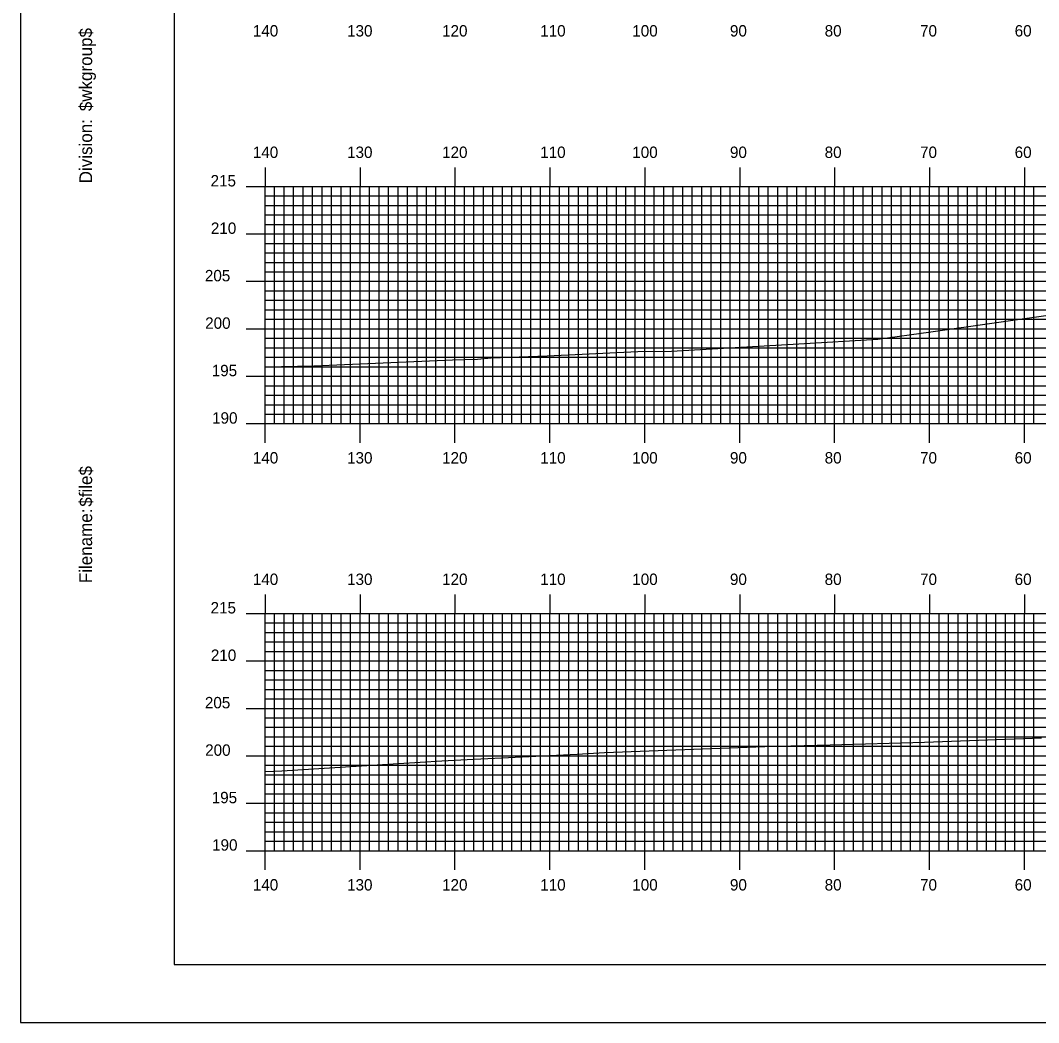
# Model space of a CAD drawing. Extents: x 1821998 to 1822342, y 442591 to 442811.
# Drawn here: x 1821998.5 to 1822105.8, y 442590.5 to 442696.2 of the extents above; entities that cross this region are included whole.
import ezdxf

# ---------------------------------------------------------------- set-up
doc = ezdxf.new("R2010")
doc.units = 0
for name, color, linetype in [('BORDER', 7, 'Continuous'), ('H_V ANNOTATION', 7, 'Continuous'), ('MAJOR', 7, 'Continuous'), ('MINOR', 7, 'Continuous'), ('PLOT BOUNDARY', 7, 'Continuous'), ('S_Roadway_Centerline', 7, 'Continuous')]:
    doc.layers.add(name, color=color, linetype=linetype)

msp = doc.modelspace()

# ---------------------------------------------------------------- linework, layer by layer
at = {"layer": 'BORDER'}
msp.add_lwpolyline([(1822014.66, 442596.67), (1822334.66, 442596.67), (1822334.66, 442806.67), (1822014.66, 442806.67)], close=True, dxfattribs=at)
at = {"layer": 'MAJOR'}
for p, q in [((1822024.26, 442680.67), (1822024.26, 442678.67)), ((1822034.26, 442680.67), (1822034.26, 442678.67)), ((1822044.26, 442680.67), (1822044.26, 442678.67)), ((1822054.26, 442680.67), (1822054.26, 442678.67)), ((1822064.26, 442680.67), (1822064.26, 442678.67)), ((1822074.26, 442680.67), (1822074.26, 442678.67)), ((1822084.26, 442680.67), (1822084.26, 442678.67)), ((1822094.26, 442680.67), (1822094.26, 442678.67)), ((1822104.26, 442680.67), (1822104.26, 442678.67)), ((1822022.25, 442678.67), (1822024.26, 442678.67)), ((1822024.26, 442678.67), (1822304.26, 442678.67)), ((1822024.26, 442653.67), (1822024.26, 442678.67)), ((1822024.26, 442653.67), (1822024.26, 442678.67)), ((1822024.26, 442678.67), (1822304.26, 442678.67)), ((1822034.26, 442653.67), (1822034.26, 442678.67)), ((1822044.26, 442653.67), (1822044.26, 442678.67)), ((1822054.26, 442653.67), (1822054.26, 442678.67)), ((1822064.26, 442653.67), (1822064.26, 442678.67)), ((1822074.26, 442653.67), (1822074.26, 442678.67)), ((1822084.26, 442653.67), (1822084.26, 442678.67)), ((1822094.26, 442653.67), (1822094.26, 442678.67)), ((1822104.26, 442653.67), (1822104.26, 442678.67)), ((1822022.25, 442673.67), (1822024.26, 442673.67)), ((1822024.26, 442673.67), (1822304.26, 442673.67)), ((1822022.25, 442668.67), (1822024.26, 442668.67)), ((1822024.26, 442668.67), (1822304.26, 442668.67)), ((1822022.25, 442663.67), (1822024.26, 442663.67)), ((1822024.26, 442663.67), (1822304.26, 442663.67)), ((1822022.25, 442658.67), (1822024.26, 442658.67)), ((1822024.26, 442658.67), (1822304.26, 442658.67)), ((1822022.25, 442653.67), (1822024.26, 442653.67)), ((1822024.26, 442653.67), (1822304.26, 442653.67)), ((1822024.26, 442653.67), (1822304.26, 442653.67)), ((1822024.26, 442651.66), (1822024.26, 442653.67)), ((1822034.26, 442651.66), (1822034.26, 442653.67)), ((1822044.26, 442651.66), (1822044.26, 442653.67)), ((1822054.26, 442651.66), (1822054.26, 442653.67)), ((1822064.26, 442651.66), (1822064.26, 442653.67)), ((1822074.26, 442651.66), (1822074.26, 442653.67)), ((1822084.26, 442651.66), (1822084.26, 442653.67)), ((1822094.26, 442651.66), (1822094.26, 442653.67)), ((1822104.26, 442651.66), (1822104.26, 442653.67)), ((1822024.26, 442635.67), (1822024.26, 442633.67)), ((1822034.26, 442635.67), (1822034.26, 442633.67)), ((1822044.26, 442635.67), (1822044.26, 442633.67)), ((1822054.26, 442635.67), (1822054.26, 442633.67)), ((1822064.26, 442635.67), (1822064.26, 442633.67)), ((1822074.26, 442635.67), (1822074.26, 442633.67)), ((1822084.26, 442635.67), (1822084.26, 442633.67)), ((1822094.26, 442635.67), (1822094.26, 442633.67)), ((1822104.26, 442635.67), (1822104.26, 442633.67)), ((1822022.25, 442633.67), (1822024.26, 442633.67)), ((1822024.26, 442633.67), (1822304.26, 442633.67)), ((1822024.26, 442608.67), (1822024.26, 442633.67)), ((1822024.26, 442608.67), (1822024.26, 442633.67)), ((1822024.26, 442633.67), (1822304.26, 442633.67)), ((1822034.26, 442608.67), (1822034.26, 442633.67)), ((1822044.26, 442608.67), (1822044.26, 442633.67)), ((1822054.26, 442608.67), (1822054.26, 442633.67)), ((1822064.26, 442608.67), (1822064.26, 442633.67)), ((1822074.26, 442608.67), (1822074.26, 442633.67)), ((1822084.26, 442608.67), (1822084.26, 442633.67)), ((1822094.26, 442608.67), (1822094.26, 442633.67)), ((1822104.26, 442608.67), (1822104.26, 442633.67)), ((1822022.25, 442628.67), (1822024.26, 442628.67)), ((1822024.26, 442628.67), (1822304.26, 442628.67)), ((1822022.25, 442623.67), (1822024.26, 442623.67)), ((1822024.26, 442623.67), (1822304.26, 442623.67)), ((1822022.25, 442618.67), (1822024.26, 442618.67)), ((1822024.26, 442618.67), (1822304.26, 442618.67)), ((1822022.25, 442613.67), (1822024.26, 442613.67)), ((1822024.26, 442613.67), (1822304.26, 442613.67)), ((1822022.25, 442608.67), (1822024.26, 442608.67)), ((1822024.26, 442608.67), (1822304.26, 442608.67)), ((1822024.26, 442608.67), (1822304.26, 442608.67)), ((1822024.26, 442606.66), (1822024.26, 442608.67)), ((1822034.26, 442606.66), (1822034.26, 442608.67)), ((1822044.26, 442606.66), (1822044.26, 442608.67)), ((1822054.26, 442606.66), (1822054.26, 442608.67)), ((1822064.26, 442606.66), (1822064.26, 442608.67)), ((1822074.26, 442606.66), (1822074.26, 442608.67)), ((1822084.26, 442606.66), (1822084.26, 442608.67)), ((1822094.26, 442606.66), (1822094.26, 442608.67)), ((1822104.26, 442606.66), (1822104.26, 442608.67))]:
    msp.add_line(p, q, dxfattribs=at)
at = {"layer": 'MINOR'}
for p, q in [((1822025.26, 442653.67), (1822025.26, 442678.67)), ((1822026.26, 442653.67), (1822026.26, 442678.67)), ((1822027.26, 442653.67), (1822027.26, 442678.67)), ((1822028.26, 442653.67), (1822028.26, 442678.67)), ((1822029.26, 442653.67), (1822029.26, 442678.67)), ((1822030.26, 442653.67), (1822030.26, 442678.67)), ((1822031.26, 442653.67), (1822031.26, 442678.67)), ((1822032.26, 442653.67), (1822032.26, 442678.67)), ((1822033.26, 442653.67), (1822033.26, 442678.67)), ((1822035.26, 442653.67), (1822035.26, 442678.67)), ((1822036.26, 442653.67), (1822036.26, 442678.67)), ((1822037.26, 442653.67), (1822037.26, 442678.67)), ((1822038.26, 442653.67), (1822038.26, 442678.67)), ((1822039.26, 442653.67), (1822039.26, 442678.67)), ((1822040.26, 442653.67), (1822040.26, 442678.67)), ((1822041.26, 442653.67), (1822041.26, 442678.67)), ((1822042.26, 442653.67), (1822042.26, 442678.67)), ((1822043.26, 442653.67), (1822043.26, 442678.67)), ((1822045.26, 442653.67), (1822045.26, 442678.67)), ((1822046.26, 442653.67), (1822046.26, 442678.67)), ((1822047.26, 442653.67), (1822047.26, 442678.67)), ((1822048.26, 442653.67), (1822048.26, 442678.67)), ((1822049.26, 442653.67), (1822049.26, 442678.67)), ((1822050.26, 442653.67), (1822050.26, 442678.67)), ((1822051.26, 442653.67), (1822051.26, 442678.67)), ((1822052.26, 442653.67), (1822052.26, 442678.67)), ((1822053.26, 442653.67), (1822053.26, 442678.67)), ((1822055.26, 442653.67), (1822055.26, 442678.67)), ((1822056.26, 442653.67), (1822056.26, 442678.67)), ((1822057.26, 442653.67), (1822057.26, 442678.67)), ((1822058.26, 442653.67), (1822058.26, 442678.67)), ((1822059.26, 442653.67), (1822059.26, 442678.67)), ((1822060.26, 442653.67), (1822060.26, 442678.67)), ((1822061.26, 442653.67), (1822061.26, 442678.67)), ((1822062.26, 442653.67), (1822062.26, 442678.67)), ((1822063.26, 442653.67), (1822063.26, 442678.67)), ((1822065.26, 442653.67), (1822065.26, 442678.67)), ((1822066.26, 442653.67), (1822066.26, 442678.67)), ((1822067.26, 442653.67), (1822067.26, 442678.67)), ((1822068.26, 442653.67), (1822068.26, 442678.67)), ((1822069.26, 442653.67), (1822069.26, 442678.67)), ((1822070.26, 442653.67), (1822070.26, 442678.67)), ((1822071.26, 442653.67), (1822071.26, 442678.67)), ((1822072.26, 442653.67), (1822072.26, 442678.67)), ((1822073.26, 442653.67), (1822073.26, 442678.67)), ((1822075.26, 442653.67), (1822075.26, 442678.67)), ((1822076.26, 442653.67), (1822076.26, 442678.67)), ((1822077.26, 442653.67), (1822077.26, 442678.67)), ((1822078.26, 442653.67), (1822078.26, 442678.67)), ((1822079.26, 442653.67), (1822079.26, 442678.67)), ((1822080.26, 442653.67), (1822080.26, 442678.67)), ((1822081.26, 442653.67), (1822081.26, 442678.67)), ((1822082.26, 442653.67), (1822082.26, 442678.67)), ((1822083.26, 442653.67), (1822083.26, 442678.67)), ((1822085.26, 442653.67), (1822085.26, 442678.67)), ((1822086.26, 442653.67), (1822086.26, 442678.67)), ((1822087.26, 442653.67), (1822087.26, 442678.67)), ((1822088.26, 442653.67), (1822088.26, 442678.67)), ((1822089.26, 442653.67), (1822089.26, 442678.67)), ((1822090.26, 442653.67), (1822090.26, 442678.67)), ((1822091.26, 442653.67), (1822091.26, 442678.67)), ((1822092.26, 442653.67), (1822092.26, 442678.67)), ((1822093.26, 442653.67), (1822093.26, 442678.67)), ((1822095.26, 442653.67), (1822095.26, 442678.67)), ((1822096.26, 442653.67), (1822096.26, 442678.67)), ((1822097.26, 442653.67), (1822097.26, 442678.67)), ((1822098.26, 442653.67), (1822098.26, 442678.67)), ((1822099.26, 442653.67), (1822099.26, 442678.67)), ((1822100.26, 442653.67), (1822100.26, 442678.67)), ((1822101.26, 442653.67), (1822101.26, 442678.67)), ((1822102.26, 442653.67), (1822102.26, 442678.67)), ((1822103.26, 442653.67), (1822103.26, 442678.67)), ((1822105.26, 442653.67), (1822105.26, 442678.67)), ((1822024.26, 442677.67), (1822304.26, 442677.67)), ((1822024.26, 442677.67), (1822026.26, 442677.67)), ((1822024.26, 442676.67), (1822304.26, 442676.67)), ((1822024.26, 442676.67), (1822026.26, 442676.67)), ((1822024.26, 442675.67), (1822304.26, 442675.67)), ((1822024.26, 442675.67), (1822026.26, 442675.67)), ((1822024.26, 442674.67), (1822304.26, 442674.67)), ((1822024.26, 442674.67), (1822026.26, 442674.67)), ((1822024.26, 442672.67), (1822304.26, 442672.67)), ((1822024.26, 442672.67), (1822026.26, 442672.67)), ((1822024.26, 442671.67), (1822304.26, 442671.67)), ((1822024.26, 442671.67), (1822026.26, 442671.67)), ((1822024.26, 442670.67), (1822304.26, 442670.67)), ((1822024.26, 442670.67), (1822026.26, 442670.67)), ((1822024.26, 442669.67), (1822304.26, 442669.67)), ((1822024.26, 442669.67), (1822026.26, 442669.67)), ((1822024.26, 442667.67), (1822304.26, 442667.67)), ((1822024.26, 442667.67), (1822026.26, 442667.67)), ((1822024.26, 442666.67), (1822304.26, 442666.67)), ((1822024.26, 442666.67), (1822026.26, 442666.67)), ((1822024.26, 442665.67), (1822304.26, 442665.67)), ((1822024.26, 442665.67), (1822026.26, 442665.67)), ((1822024.26, 442664.67), (1822304.26, 442664.67)), ((1822024.26, 442664.67), (1822026.26, 442664.67)), ((1822024.26, 442662.67), (1822304.26, 442662.67)), ((1822024.26, 442662.67), (1822026.26, 442662.67)), ((1822024.26, 442661.67), (1822304.26, 442661.67)), ((1822024.26, 442661.67), (1822026.26, 442661.67)), ((1822024.26, 442660.67), (1822304.26, 442660.67)), ((1822024.26, 442660.67), (1822026.26, 442660.67)), ((1822024.26, 442659.67), (1822304.26, 442659.67)), ((1822024.26, 442659.67), (1822026.26, 442659.67)), ((1822024.26, 442657.67), (1822304.26, 442657.67)), ((1822024.26, 442657.67), (1822026.26, 442657.67)), ((1822024.26, 442656.67), (1822304.26, 442656.67)), ((1822024.26, 442656.67), (1822026.26, 442656.67)), ((1822024.26, 442655.67), (1822304.26, 442655.67)), ((1822024.26, 442655.67), (1822026.26, 442655.67)), ((1822024.26, 442654.67), (1822304.26, 442654.67)), ((1822024.26, 442654.67), (1822026.26, 442654.67)), ((1822025.26, 442608.67), (1822025.26, 442633.67)), ((1822026.26, 442608.67), (1822026.26, 442633.67)), ((1822027.26, 442608.67), (1822027.26, 442633.67)), ((1822028.26, 442608.67), (1822028.26, 442633.67)), ((1822029.26, 442608.67), (1822029.26, 442633.67)), ((1822030.26, 442608.67), (1822030.26, 442633.67)), ((1822031.26, 442608.67), (1822031.26, 442633.67)), ((1822032.26, 442608.67), (1822032.26, 442633.67)), ((1822033.26, 442608.67), (1822033.26, 442633.67)), ((1822035.26, 442608.67), (1822035.26, 442633.67)), ((1822036.26, 442608.67), (1822036.26, 442633.67)), ((1822037.26, 442608.67), (1822037.26, 442633.67)), ((1822038.26, 442608.67), (1822038.26, 442633.67)), ((1822039.26, 442608.67), (1822039.26, 442633.67)), ((1822040.26, 442608.67), (1822040.26, 442633.67)), ((1822041.26, 442608.67), (1822041.26, 442633.67)), ((1822042.26, 442608.67), (1822042.26, 442633.67)), ((1822043.26, 442608.67), (1822043.26, 442633.67)), ((1822045.26, 442608.67), (1822045.26, 442633.67)), ((1822046.26, 442608.67), (1822046.26, 442633.67)), ((1822047.26, 442608.67), (1822047.26, 442633.67)), ((1822048.26, 442608.67), (1822048.26, 442633.67)), ((1822049.26, 442608.67), (1822049.26, 442633.67)), ((1822050.26, 442608.67), (1822050.26, 442633.67)), ((1822051.26, 442608.67), (1822051.26, 442633.67)), ((1822052.26, 442608.67), (1822052.26, 442633.67)), ((1822053.26, 442608.67), (1822053.26, 442633.67)), ((1822055.26, 442608.67), (1822055.26, 442633.67)), ((1822056.26, 442608.67), (1822056.26, 442633.67)), ((1822057.26, 442608.67), (1822057.26, 442633.67)), ((1822058.26, 442608.67), (1822058.26, 442633.67)), ((1822059.26, 442608.67), (1822059.26, 442633.67)), ((1822060.26, 442608.67), (1822060.26, 442633.67)), ((1822061.26, 442608.67), (1822061.26, 442633.67)), ((1822062.26, 442608.67), (1822062.26, 442633.67)), ((1822063.26, 442608.67), (1822063.26, 442633.67)), ((1822065.26, 442608.67), (1822065.26, 442633.67)), ((1822066.26, 442608.67), (1822066.26, 442633.67)), ((1822067.26, 442608.67), (1822067.26, 442633.67)), ((1822068.26, 442608.67), (1822068.26, 442633.67)), ((1822069.26, 442608.67), (1822069.26, 442633.67)), ((1822070.26, 442608.67), (1822070.26, 442633.67)), ((1822071.26, 442608.67), (1822071.26, 442633.67)), ((1822072.26, 442608.67), (1822072.26, 442633.67)), ((1822073.26, 442608.67), (1822073.26, 442633.67)), ((1822075.26, 442608.67), (1822075.26, 442633.67)), ((1822076.26, 442608.67), (1822076.26, 442633.67)), ((1822077.26, 442608.67), (1822077.26, 442633.67)), ((1822078.26, 442608.67), (1822078.26, 442633.67)), ((1822079.26, 442608.67), (1822079.26, 442633.67)), ((1822080.26, 442608.67), (1822080.26, 442633.67)), ((1822081.26, 442608.67), (1822081.26, 442633.67)), ((1822082.26, 442608.67), (1822082.26, 442633.67)), ((1822083.26, 442608.67), (1822083.26, 442633.67)), ((1822085.26, 442608.67), (1822085.26, 442633.67)), ((1822086.26, 442608.67), (1822086.26, 442633.67)), ((1822087.26, 442608.67), (1822087.26, 442633.67)), ((1822088.26, 442608.67), (1822088.26, 442633.67)), ((1822089.26, 442608.67), (1822089.26, 442633.67)), ((1822090.26, 442608.67), (1822090.26, 442633.67)), ((1822091.26, 442608.67), (1822091.26, 442633.67)), ((1822092.26, 442608.67), (1822092.26, 442633.67)), ((1822093.26, 442608.67), (1822093.26, 442633.67)), ((1822095.26, 442608.67), (1822095.26, 442633.67)), ((1822096.26, 442608.67), (1822096.26, 442633.67)), ((1822097.26, 442608.67), (1822097.26, 442633.67)), ((1822098.26, 442608.67), (1822098.26, 442633.67)), ((1822099.26, 442608.67), (1822099.26, 442633.67)), ((1822100.26, 442608.67), (1822100.26, 442633.67)), ((1822101.26, 442608.67), (1822101.26, 442633.67)), ((1822102.26, 442608.67), (1822102.26, 442633.67)), ((1822103.26, 442608.67), (1822103.26, 442633.67)), ((1822105.26, 442608.67), (1822105.26, 442633.67)), ((1822024.26, 442632.67), (1822304.26, 442632.67)), ((1822024.26, 442632.67), (1822026.26, 442632.67)), ((1822024.26, 442631.67), (1822304.26, 442631.67)), ((1822024.26, 442631.67), (1822026.26, 442631.67)), ((1822024.26, 442630.67), (1822304.26, 442630.67)), ((1822024.26, 442630.67), (1822026.26, 442630.67)), ((1822024.26, 442629.67), (1822304.26, 442629.67)), ((1822024.26, 442629.67), (1822026.26, 442629.67)), ((1822024.26, 442627.67), (1822304.26, 442627.67)), ((1822024.26, 442627.67), (1822026.26, 442627.67)), ((1822024.26, 442626.67), (1822304.26, 442626.67)), ((1822024.26, 442626.67), (1822026.26, 442626.67)), ((1822024.26, 442625.67), (1822304.26, 442625.67)), ((1822024.26, 442625.67), (1822026.26, 442625.67)), ((1822024.26, 442624.67), (1822304.26, 442624.67)), ((1822024.26, 442624.67), (1822026.26, 442624.67)), ((1822024.26, 442622.67), (1822304.26, 442622.67)), ((1822024.26, 442622.67), (1822026.26, 442622.67)), ((1822024.26, 442621.67), (1822304.26, 442621.67)), ((1822024.26, 442621.67), (1822026.26, 442621.67)), ((1822024.26, 442620.67), (1822304.26, 442620.67)), ((1822024.26, 442620.67), (1822026.26, 442620.67)), ((1822024.26, 442619.67), (1822304.26, 442619.67)), ((1822024.26, 442619.67), (1822026.26, 442619.67)), ((1822024.26, 442617.67), (1822304.26, 442617.67)), ((1822024.26, 442617.67), (1822026.26, 442617.67)), ((1822024.26, 442616.67), (1822304.26, 442616.67)), ((1822024.26, 442616.67), (1822026.26, 442616.67)), ((1822024.26, 442615.67), (1822304.26, 442615.67)), ((1822024.26, 442615.67), (1822026.26, 442615.67)), ((1822024.26, 442614.67), (1822304.26, 442614.67)), ((1822024.26, 442614.67), (1822026.26, 442614.67)), ((1822024.26, 442612.67), (1822304.26, 442612.67)), ((1822024.26, 442612.67), (1822026.26, 442612.67)), ((1822024.26, 442611.67), (1822304.26, 442611.67)), ((1822024.26, 442611.67), (1822026.26, 442611.67)), ((1822024.26, 442610.67), (1822304.26, 442610.67)), ((1822024.26, 442610.67), (1822026.26, 442610.67)), ((1822024.26, 442609.67), (1822304.26, 442609.67)), ((1822024.26, 442609.67), (1822026.26, 442609.67))]:
    msp.add_line(p, q, dxfattribs=at)
at = {"layer": 'PLOT BOUNDARY'}
msp.add_lwpolyline([(1821998.47, 442590.55), (1822338.47, 442590.55), (1822338.47, 442810.55), (1821998.47, 442810.55)], close=True, dxfattribs=at)
at = {"layer": 'S_Roadway_Centerline'}
for points in [[(1822024.26, 442659.65), (1822029.39, 442659.75), (1822043.99, 442660.38), (1822046.65, 442660.47), (1822048.06, 442660.61), (1822053.98, 442660.81), (1822063.52, 442661.27), (1822067.07, 442661.32), (1822080.49, 442662.08), (1822088.82, 442662.58), (1822094.4, 442663.34), (1822107.97, 442665.29)], [(1822024.26, 442617.03), (1822026.03, 442617.08), (1822038.31, 442617.87), (1822042.88, 442618.12), (1822045.56, 442618.27), (1822057.12, 442618.85), (1822060.02, 442619), (1822060.97, 442619.04), (1822076.89, 442619.66), (1822083.79, 442619.81), (1822093.73, 442620.12), (1822106.05, 442620.56)]]:
    msp.add_lwpolyline(points, dxfattribs=at)

# ---------------------------------------------------------------- texts
at = {"layer": 'BORDER'}
for s, p in [('$wkgroup$', (1822006.03, 442686.6)), ('Division:', (1822006.03, 442679)), ('$file$', (1822006.03, 442644.92)), ('Filename:', (1822006.03, 442636.86))]:
    msp.add_text(s, height=1.339, rotation=90, dxfattribs=at).set_placement(p)
at = {"layer": 'H_V ANNOTATION'}
for s, p in [('140', (1822022.96, 442694.47)), ('130', (1822032.89, 442694.47)), ('120', (1822042.9, 442694.47)), ('110', (1822053.24, 442694.47)), ('100', (1822062.94, 442694.47)), ('90', (1822073.23, 442694.47)), ('80', (1822083.21, 442694.47)), ('70', (1822093.26, 442694.47)), ('60', (1822103.23, 442694.47)), ('140', (1822022.96, 442681.67)), ('130', (1822032.89, 442681.67)), ('120', (1822042.9, 442681.67)), ('110', (1822053.24, 442681.67)), ('100', (1822062.94, 442681.67)), ('90', (1822073.23, 442681.67)), ('80', (1822083.21, 442681.67)), ('70', (1822093.26, 442681.67)), ('60', (1822103.23, 442681.67)), ('215', (1822018.51, 442678.67)), ('210', (1822018.54, 442673.67)), ('205', (1822017.91, 442668.67)), ('200', (1822017.94, 442663.67)), ('195', (1822018.63, 442658.67)), ('190', (1822018.67, 442653.67)), ('140', (1822022.96, 442649.47)), ('130', (1822032.89, 442649.47)), ('120', (1822042.9, 442649.47)), ('110', (1822053.24, 442649.47)), ('100', (1822062.94, 442649.47)), ('90', (1822073.23, 442649.47)), ('80', (1822083.21, 442649.47)), ('70', (1822093.26, 442649.47)), ('60', (1822103.23, 442649.47)), ('140', (1822022.96, 442636.67)), ('130', (1822032.89, 442636.67)), ('120', (1822042.9, 442636.67)), ('110', (1822053.24, 442636.67)), ('100', (1822062.94, 442636.67)), ('90', (1822073.23, 442636.67)), ('80', (1822083.21, 442636.67)), ('70', (1822093.26, 442636.67)), ('60', (1822103.23, 442636.67)), ('215', (1822018.51, 442633.67)), ('210', (1822018.54, 442628.67)), ('205', (1822017.91, 442623.67)), ('200', (1822017.94, 442618.67)), ('195', (1822018.63, 442613.67)), ('190', (1822018.67, 442608.67)), ('140', (1822022.96, 442604.47)), ('130', (1822032.89, 442604.47)), ('120', (1822042.9, 442604.47)), ('110', (1822053.24, 442604.47)), ('100', (1822062.94, 442604.47)), ('90', (1822073.23, 442604.47)), ('80', (1822083.21, 442604.47)), ('70', (1822093.26, 442604.47)), ('60', (1822103.23, 442604.47))]:
    msp.add_text(s, height=1.2, dxfattribs=at).set_placement(p)
at = {"layer": 'MAJOR'}
for p in [(1822024.25, 442653.67), (1822024.25, 442608.67)]:
    msp.add_text('-', height=0.012, dxfattribs=at).set_placement(p)

doc.saveas('drawing.dxf')
